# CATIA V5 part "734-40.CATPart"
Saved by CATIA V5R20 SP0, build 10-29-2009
Part number: 734-40
Bounding box of the stored display mesh (mm): x -33 to 33, y -32.999 to 32.999, z -47 to 63
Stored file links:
  C:\Users\Utente\Desktop\IO LAVORO\3D X SITO CF\X SITO\734\734-40.CATPart
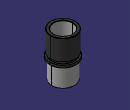
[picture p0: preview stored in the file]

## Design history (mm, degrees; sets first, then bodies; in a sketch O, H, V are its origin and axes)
Set1
  DatumSurface1 to DatumSurface25 "734-40 nau"
Body1 (main body)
